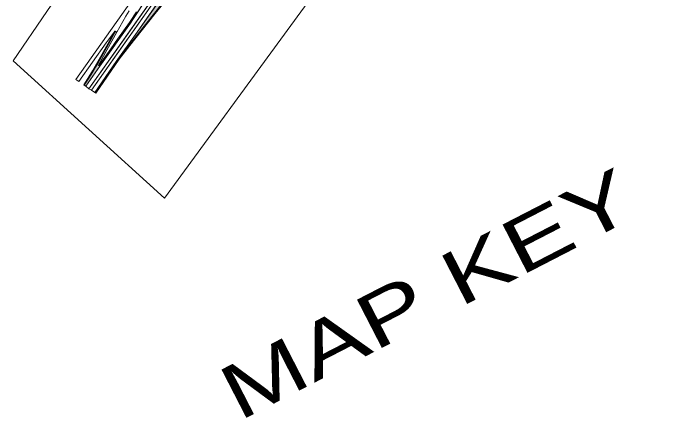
# Model space of a CAD drawing. Extents: x 2356431 to 2371438, y 6972864 to 6982525.
# Drawn here: x 2356430.8 to 2356695.4, y 6974300.2 to 6974463.1 of the extents above; entities that cross this region are included whole.
import ezdxf

# ---------------------------------------------------------------- set-up
doc = ezdxf.new("R2010")
doc.units = 0
doc.header["$LTSCALE"] = 5.6
for name, color, linetype, lineweight in [('1', 7, 'Continuous', 25), ('10', 7, 'Continuous', 13), ('11', 7, 'Continuous', 13), ('62', 7, 'Continuous', 25), ('9', 7, 'Continuous', 13)]:
    doc.layers.add(name, color=color, linetype=linetype, lineweight=lineweight)

msp = doc.modelspace()

# ---------------------------------------------------------------- hatches: boundary and pattern name
at = {"layer": '10'}
msp.add_hatch(color=256, dxfattribs=at).paths.add_polyline_path([(2356459.215, 6974434.241), (2356461.281, 6974437.47), (2356462.781, 6974439.841), (2356464.395, 6974442.777), (2356465.964, 6974445.514), (2356467.782, 6974448.678), (2356469.581, 6974451.947), (2356471.392, 6974455.3), (2356471.854, 6974455.902), (2356471.978, 6974455.816), (2356470.732, 6974453.546), (2356467.73, 6974448.069), (2356464.46, 6974442.271), (2356463.248, 6974440.117), (2356461.92, 6974437.995), (2356459.447, 6974434.072)])
at = {"layer": '11'}
for points in [[(2356490.784, 6974466.994), (2356489.535, 6974467.878), (2356480.799, 6974455.527), (2356472.354, 6974443.705)], [(2356472.602, 6974455.43), (2356465.177, 6974442.199), (2356465.201, 6974442.025), (2356465.753, 6974441.752), (2356460.032, 6974433.678), (2356459.437, 6974434.088), (2356461.57, 6974437.411), (2356462.614, 6974439.063), (2356463.423, 6974440.509), (2356464.193, 6974441.763), (2356464.99, 6974443.158), (2356469.828, 6974451.791), (2356471.935, 6974455.74)]]:
    msp.add_hatch(color=256, dxfattribs=at).paths.add_polyline_path(points)

# ---------------------------------------------------------------- linework, layer by layer
at = {"layer": '1', "lineweight": 13}
msp.add_lwpolyline([(2356430.785, 6974443.876), (2356593.614, 6974682.372), (2356598.063, 6974893.324), (2356675.176, 6974911.84), (2356695.376, 6974666.854), (2356491.76, 6974388.684)], close=True, dxfattribs=at)
at = {"layer": '10'}
for points in [[(2356573.798, 6974593.591), (2356575.127, 6974595.027), (2356576.51, 6974596.522), (2356579.011, 6974599.155), (2356570.459, 6974587.001), (2356563.2, 6974576.747), (2356461.322, 6974432.697), (2356460.032, 6974433.678), (2356465.753, 6974441.752), (2356478.18, 6974459.338), (2356485.543, 6974470.683), (2356511.227, 6974507.02), (2356518.187, 6974517.315), (2356523.662, 6974526.171), (2356524.661, 6974525.675), (2356525.402, 6974525.169)], [(2356461.322, 6974432.697), (2356474.84, 6974451.768), (2356488.4, 6974471.052), (2356507.82, 6974498.473), (2356527.034, 6974525.661), (2356541.428, 6974546.012), (2356553.129, 6974562.534), (2356562.994, 6974576.602), (2356563.535, 6974575.475), (2356556.492, 6974565.08), (2356553.436, 6974560.385), (2356540.922, 6974543.097), (2356524.43, 6974520.049), (2356508.546, 6974497.611), (2356462.311, 6974432.075)], [(2356517.602, 6974510.224), (2356492.756, 6974475.136), (2356480.156, 6974457.28), (2356475.825, 6974451.121), (2356462.343, 6974432.087), (2356463.674, 6974431.165), (2356472.354, 6974443.705), (2356480.799, 6974455.527), (2356507.62, 6974493.464), (2356508.6, 6974494.785), (2356512.748, 6974500.042), (2356519.617, 6974508.641)], [(2356459.215, 6974434.241), (2356461.281, 6974437.47), (2356462.781, 6974439.841), (2356464.395, 6974442.777), (2356465.964, 6974445.514), (2356467.782, 6974448.678), (2356469.581, 6974451.947), (2356471.392, 6974455.3), (2356471.854, 6974455.902), (2356471.978, 6974455.816), (2356470.732, 6974453.546), (2356467.73, 6974448.069), (2356464.46, 6974442.271), (2356463.248, 6974440.117), (2356461.92, 6974437.995), (2356459.447, 6974434.072)]]:
    msp.add_lwpolyline(points, close=True, dxfattribs=at)
for points in [[(2356491.062, 6974466.743), (2356488.063, 6974463.007), (2356477.812, 6974450.053), (2356473.507, 6974444.577), (2356464.048, 6974430.916), (2356463.695, 6974431.174), (2356472.247, 6974443.548), (2356474.794, 6974446.781), (2356476.004, 6974448.332), (2356480.984, 6974454.61), (2356490.799, 6974467.005)], [(2356483.51, 6974467.58), (2356480.447, 6974462.841), (2356478.021, 6974459.076), (2356465.747, 6974441.802), (2356465.269, 6974442.005), (2356470.201, 6974448.809), (2356472.85, 6974452.591), (2356477.631, 6974459.304), (2356480.453, 6974463.644)]]:
    msp.add_lwpolyline(points, dxfattribs=at)
at = {"layer": '11'}
for points in [[(2356490.784, 6974466.994), (2356489.535, 6974467.878), (2356480.799, 6974455.527), (2356472.354, 6974443.705)], [(2356472.602, 6974455.43), (2356465.177, 6974442.199), (2356465.201, 6974442.025), (2356465.753, 6974441.752), (2356460.032, 6974433.678), (2356459.437, 6974434.088), (2356461.57, 6974437.411), (2356462.614, 6974439.063), (2356463.423, 6974440.509), (2356464.193, 6974441.763), (2356464.99, 6974443.158), (2356469.828, 6974451.791), (2356471.935, 6974455.74)]]:
    msp.add_lwpolyline(points, close=True, dxfattribs=at)
at = {"layer": '9'}
msp.add_lwpolyline([(2356477.511, 6974463.986), (2356476.237, 6974461.906), (2356472.602, 6974455.43), (2356471.893, 6974455.835), (2356471.876, 6974455.842), (2356471.86, 6974455.848), (2356471.841, 6974455.848), (2356471.827, 6974455.847), (2356471.807, 6974455.84), (2356471.792, 6974455.832), (2356471.772, 6974455.81), (2356471.545, 6974455.516), (2356469.996, 6974453.512), (2356469.013, 6974452.249), (2356468.29, 6974451.193), (2356457.244, 6974435.58), (2356456.068, 6974436.411), (2356558.75, 6974581.633)], dxfattribs=at)

# ---------------------------------------------------------------- texts
at = {"layer": '62', "width": 1.4}
msp.add_text('MAP KEY', height=21.87, rotation=27.268, dxfattribs=at).set_placement((2356521.769, 6974298.659))

doc.saveas('drawing.dxf')
